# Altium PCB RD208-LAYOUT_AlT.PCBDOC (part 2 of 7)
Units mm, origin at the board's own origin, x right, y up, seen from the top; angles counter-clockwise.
Board outline 240 x 150 mm, 6 copper layers (TOP, Mid-Layer 1, Mid-Layer 2, Mid-Layer 3, Mid-Layer 4, BOTTOM), stack 1.422 mm thick; 773 components, 409 nets, 3936 pads, 97 vias.
Unrouted connection lines stored in the file: 1.
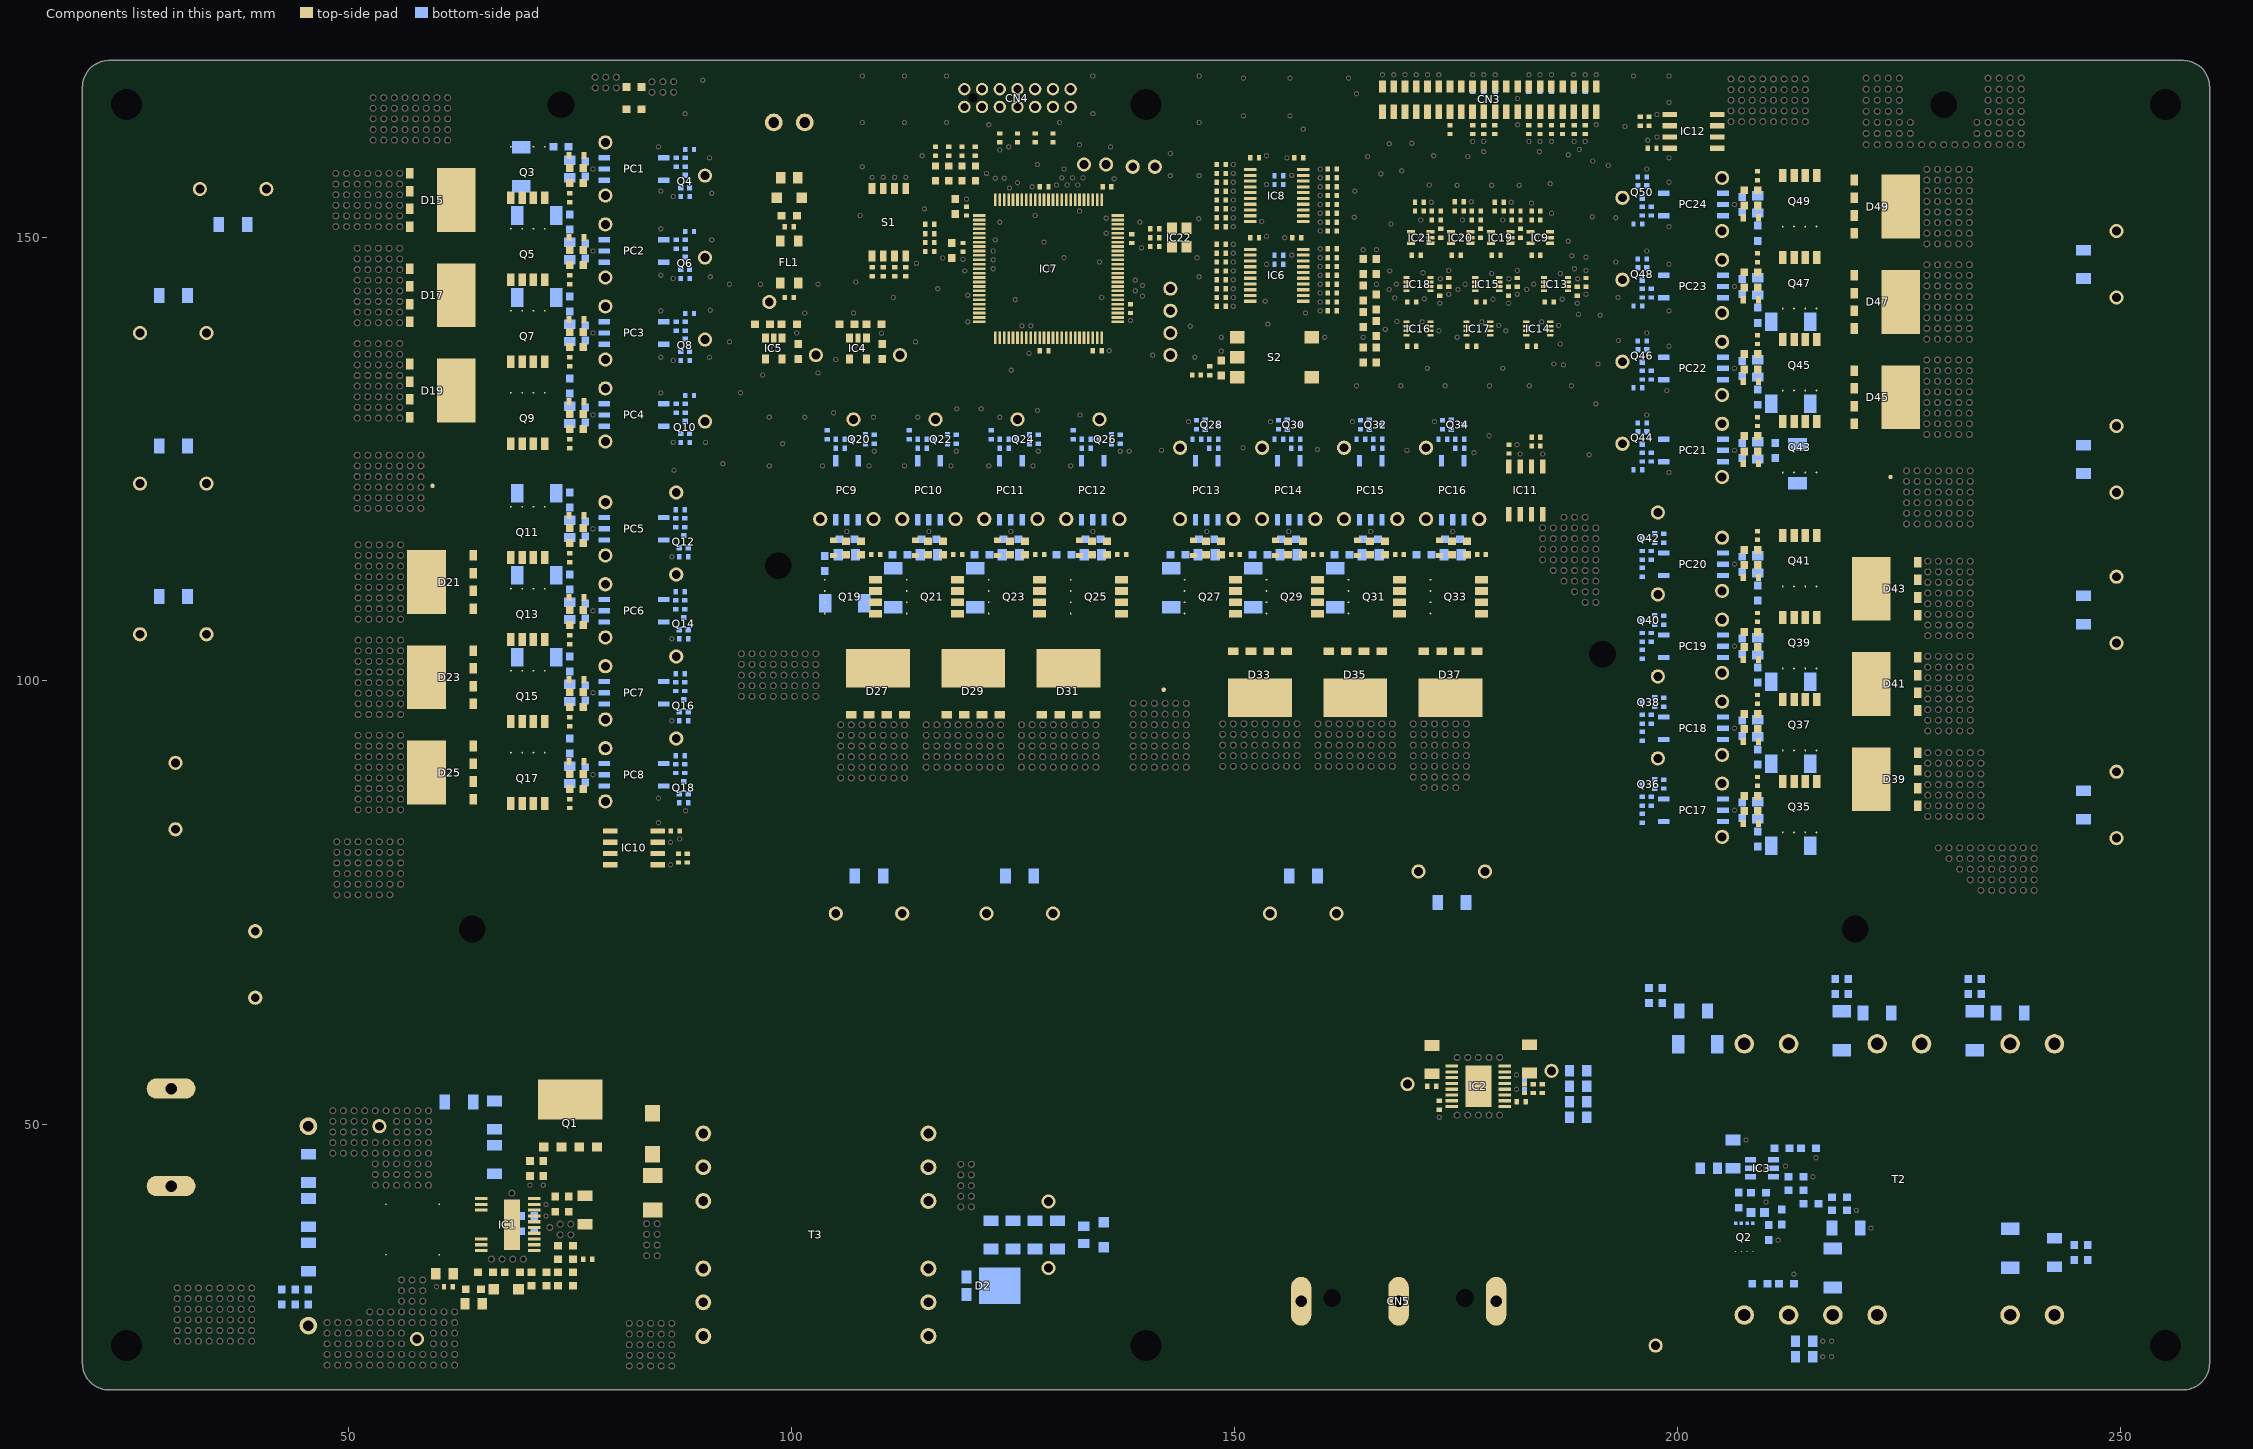
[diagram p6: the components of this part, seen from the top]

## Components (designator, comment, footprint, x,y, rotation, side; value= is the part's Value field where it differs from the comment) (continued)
TP32 "TP-TH1.0-L1.6-D-SP" TP-TH1.0-L1.6-D-SP 79,92.4 r180 top
TP33 "TP-TH1.0-L1.6-D-SP" TP-TH1.0-L1.6-D-SP 107,129.5 r270 top
TP34 "TP-TH1.0-L1.6-D-SP" TP-TH1.0-L1.6-D-SP 116.25,129.5 r270 top
TP35 "TP-TH1.0-L1.6-D-SP" TP-TH1.0-L1.6-D-SP 125.5,129.5 r270 top
TP36 "TP-TH1.0-L1.6-D-SP" TP-TH1.0-L1.6-D-SP 134.75,129.5 r270 top
TP37 "TP-TH1.0-L1.6-D-SP" TP-TH1.0-L1.6-D-SP 143.85,126.3 r270 top
TP38 "TP-TH1.0-L1.6-D-SP" TP-TH1.0-L1.6-D-SP 153.1,126.3 r270 top
TP39 "TP-TH1.0-L1.6-D-SP" TP-TH1.0-L1.6-D-SP 162.35,126.3 r270 top
TP40 "TP-TH1.0-L1.6-D-SP" TP-TH1.0-L1.6-D-SP 171.6,126.3 r270 top
TP41 "TP-TH1.0-L1.6-D-SP" TP-TH1.0-L1.6-D-SP 103.25,118.25 r270 top
TP42 "TP-TH1.0-L1.6-D-SP" TP-TH1.0-L1.6-D-SP 112.5,118.25 r270 top
TP43 "TP-TH1.0-L1.6-D-SP" TP-TH1.0-L1.6-D-SP 121.75,118.25 r270 top
TP44 "TP-TH1.0-L1.6-D-SP" TP-TH1.0-L1.6-D-SP 131,118.25 r270 top
TP45 "TP-TH1.0-L1.6-D-SP" TP-TH1.0-L1.6-D-SP 143.85,118.25 r270 top
TP46 "TP-TH1.0-L1.6-D-SP" TP-TH1.0-L1.6-D-SP 153.1,118.25 r270 top
TP47 "TP-TH1.0-L1.6-D-SP" TP-TH1.0-L1.6-D-SP 162.35,118.25 r270 top
TP48 "TP-TH1.0-L1.6-D-SP" TP-TH1.0-L1.6-D-SP 171.6,118.25 r270 top
TP49 "TP-TH1.0-L1.6-D-SP" TP-TH1.0-L1.6-D-SP 197.75,91.25 r0 top
TP50 "TP-TH1.0-L1.6-D-SP" TP-TH1.0-L1.6-D-SP 197.75,100.5 r0 top
TP51 "TP-TH1.0-L1.6-D-SP" TP-TH1.0-L1.6-D-SP 197.75,109.75 r0 top
TP52 "TP-TH1.0-L1.6-D-SP" TP-TH1.0-L1.6-D-SP 197.75,119 r0 top
TP53 "TP-TH1.0-L1.6-D-SP" TP-TH1.0-L1.6-D-SP 193.75,126.75 r0 top
TP54 "TP-TH1.0-L1.6-D-SP" TP-TH1.0-L1.6-D-SP 193.75,136 r0 top
TP55 "TP-TH1.0-L1.6-D-SP" TP-TH1.0-L1.6-D-SP 193.75,145.25 r0 top
TP56 "TP-TH1.0-L1.6-D-SP" TP-TH1.0-L1.6-D-SP 193.75,154.5 r0 top
TP57 "TP-TH1.0-L1.6-D-SP" TP-TH1.0-L1.6-D-SP 205,82.4 r0 top
TP58 "TP-TH1.0-L1.6-D-SP" TP-TH1.0-L1.6-D-SP 205,91.65 r0 top
TP59 "TP-TH1.0-L1.6-D-SP" TP-TH1.0-L1.6-D-SP 205,100.9 r0 top
TP60 "TP-TH1.0-L1.6-D-SP" TP-TH1.0-L1.6-D-SP 205,110.15 r0 top
TP61 "TP-TH1.0-L1.6-D-SP" TP-TH1.0-L1.6-D-SP 205,123 r0 top
TP62 "TP-TH1.0-L1.6-D-SP" TP-TH1.0-L1.6-D-SP 205,132.25 r0 top
TP63 "TP-TH1.0-L1.6-D-SP" TP-TH1.0-L1.6-D-SP 205,141.5 r0 top
TP64 "TP-TH1.0-L1.6-D-SP" TP-TH1.0-L1.6-D-SP 205,150.75 r0 top
TP65 "TP-TH1.0-L1.6-D-SP" TP-TH1.0-L1.6-D-SP 79,154.75 r180 top
TP66 "TP-TH1.0-L1.6-D-SP" TP-TH1.0-L1.6-D-SP 79,145.5 r180 top
TP67 "TP-TH1.0-L1.6-D-SP" TP-TH1.0-L1.6-D-SP 79,136.25 r180 top
TP68 "TP-TH1.0-L1.6-D-SP" TP-TH1.0-L1.6-D-SP 79,127 r180 top
TP69 "TP-TH1.0-L1.6-D-SP" TP-TH1.0-L1.6-D-SP 79,114.15 r180 top
TP70 "TP-TH1.0-L1.6-D-SP" TP-TH1.0-L1.6-D-SP 79,104.9 r180 top
TP71 "TP-TH1.0-L1.6-D-SP" TP-TH1.0-L1.6-D-SP 79,95.65 r180 top
TP72 "TP-TH1.0-L1.6-D-SP" TP-TH1.0-L1.6-D-SP 79,86.4 r180 top
TP73 "TP-TH1.0-L1.6-D-SP" TP-TH1.0-L1.6-D-SP 109.25,118.25 r270 top
TP74 "TP-TH1.0-L1.6-D-SP" TP-TH1.0-L1.6-D-SP 118.5,118.25 r270 top
TP75 "TP-TH1.0-L1.6-D-SP" TP-TH1.0-L1.6-D-SP 127.75,118.25 r270 top
TP76 "TP-TH1.0-L1.6-D-SP" TP-TH1.0-L1.6-D-SP 137,118.25 r270 top
TP77 "TP-TH1.0-L1.6-D-SP" TP-TH1.0-L1.6-D-SP 149.85,118.25 r270 top
TP78 "TP-TH1.0-L1.6-D-SP" TP-TH1.0-L1.6-D-SP 159.1,118.25 r270 top
TP79 "TP-TH1.0-L1.6-D-SP" TP-TH1.0-L1.6-D-SP 168.35,118.25 r270 top
TP80 "TP-TH1.0-L1.6-D-SP" TP-TH1.0-L1.6-D-SP 177.6,118.25 r270 top
TP81 "TP-TH1.0-L1.6-D-SP" TP-TH1.0-L1.6-D-SP 205,88.4 r0 top
TP82 "TP-TH1.0-L1.6-D-SP" TP-TH1.0-L1.6-D-SP 205,97.65 r0 top
TP83 "TP-TH1.0-L1.6-D-SP" TP-TH1.0-L1.6-D-SP 205,106.9 r0 top
TP84 "TP-TH1.0-L1.6-D-SP" TP-TH1.0-L1.6-D-SP 205,116.15 r0 top
TP85 "TP-TH1.0-L1.6-D-SP" TP-TH1.0-L1.6-D-SP 205,129 r0 top
TP86 "TP-TH1.0-L1.6-D-SP" TP-TH1.0-L1.6-D-SP 205,138.25 r0 top
TP87 "TP-TH1.0-L1.6-D-SP" TP-TH1.0-L1.6-D-SP 205,147.5 r0 top
TP88 "TP-TH1.0-L1.6-D-SP" TP-TH1.0-L1.6-D-SP 205,156.75 r0 top

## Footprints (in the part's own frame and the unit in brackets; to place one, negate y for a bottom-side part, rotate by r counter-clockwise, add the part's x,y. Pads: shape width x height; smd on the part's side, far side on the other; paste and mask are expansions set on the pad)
1843606-D-SP [mm] "KC00080BKP"
  round 2 / inner round 0 / far side round 2 hole 1.2 paste-2.1 mask+0: 1(1.75,0) 2(-1.75,0)
  silkscreen extent -4.2,-4.25 4.2,3
750342424-D-SP [mm] "KC00080BKP"
  round 2.2 / inner round 0 / far side round 2.2 hole 1.4 paste-2.3 mask+0: 1(-17.5,-15.3) 2(-12.5,-15.3) 3(-7.5,-15.3) 4(-2.5,-15.3) 7(12.5,-15.3) 8(17.5,-15.3) 9(17.5,15.3) 10(12.5,15.3) 12(2.5,15.3) 13(-2.5,15.3) 15(-12.5,15.3) 16(-17.5,15.3)
  silkscreen extent -24.5,-20.95 24.5,20.95
878311420-D-SP [mm] "KC00080BKP"
  round 1.4 / inner round 0 / far side round 1.4 hole 0.9 paste-1.5 mask+0: 1(-6,-1) 2(-6,1) 3(-4,-1) 4(-4,1) 5(-2,-1) 6(-2,1) 7(0,-1) 8(0,1) 9(2,-1) 10(2,1) 11(4,-1) 12(4,1) 13(6,-1) 14(6,1)
  round 0 hole 1 unplated paste-1.1 mask+0: ""(5,0)
  silkscreen extent -8.42,-3.25 8.42,3.25
ABRACON-ASE-3.2x2.5-R-SP [mm] "KC00080BKP"
  rect 1.3x1.1 smd paste-1.4 mask+0: 1(-1.05,-0.825) 2(1.05,-0.825) 3(1.05,0.825) 4(-1.05,0.825)
  silkscreen extent -2.1,-1.75 2.1,1.75
C1005_R_SP#1 [mm] "KC00080BKP"
  rect 0.5x0.6 smd paste-0.7 mask+0: 1(-0.5,0) 2(0.5,0)
  silkscreen extent -0.5,-0.65 0.5,0.65
C1005_R_SP#2 [mm] "KC00080BKP"
  rect 0.5x0.6 smd paste-0.7 mask+0: 1(0.5,0) 2(-0.5,0)
C1608_R_SP#1 [mm] "KC00080BKP"
  rect 0.9x0.85 smd paste-1 mask+0: 1(-0.85,0) 2(0.85,0)
  silkscreen extent -0.8,-0.77 0.8,0.77
C1608_R_SP#2 [mm] "KC00080BKP"
  rect 0.9x0.85 smd paste-1 mask+0: 1(0.85,0) 2(-0.85,0)
  silkscreen extent -0.8,-0.77 0.8,0.77
C2125_R_SP#1 [mm] "KC00080BKP"
  rect 1.05x1.3 smd paste-1.4 mask+0: 1(-0.975,0) 2(0.975,0)
C2125_R_SP#2 [mm] "KC00080BKP"
  rect 1.05x1.3 smd paste-1.4 mask+0: 1(0.975,0) 2(-0.975,0)
  silkscreen extent -1,1 1,1
C3216-R-SP#1 [mm] "KC00080BKP"
  rect 1.2x1.7 smd paste-1.8 mask+0: 1(1.6,0) 2(-1.6,0)
  silkscreen extent -1.6,-1.2 1.6,1.2
C3216-R-SP#2 [mm] "KC00080BKP"
  rect 1.2x1.7 smd paste-1.8 mask+0: 1(-1.6,0) 2(1.6,0)
  silkscreen extent -1.6,-1.2 1.6,1.2
C5750-R-SP [mil] "KC00080BKP"
  round 7 smd paste-7 mask+0: 1(-112.2,0) 2(112.2,0)
  silkscreen extent -157,-118 157,118
C-27.0x10.5-P22.5-D-SP [mm] "KC00080BKP"
  round 2 / inner round 0 / far side round 2 hole 1.2 paste-2.1 mask+0: 1(-11.25,0) 2(11.25,0)
  silkscreen extent -13.75,-5.5 13.75,5.5
CA-D18.0-P7.5-D-SP [mm] "KC00080BKP"
  round 1.6 / inner round 0 / far side round 1.6 hole 1 paste-1.7 mask+0: 1(-3.75,0) 2(3.75,0)
  silkscreen extent -10.7,-9.25 9.25,9.25
CA-NICHEMI-D16.0-P7.5-D-SP [mm] "KC00080BKP"
  round 1.6 / inner round 0 / far side round 1.6 hole 1 paste-1.7 mask+0: 1(-3.75,0) 2(3.75,0)
  silkscreen extent -9.7,-8.25 8.25,8.25
CHS-04TB-R-SP [mm] "KC00080BKP"
  rect 0.76x1.27 smd paste-1.37 mask+0: 1(-1.905,-3.81) 2(-0.635,-3.81) 3(0.635,-3.81) 4(1.905,-3.81) 5(1.905,3.81) 6(0.635,3.81) 7(-0.635,3.81) 8(-1.905,3.81)
  silkscreen extent -3.44,-2.8 3.46,2.8
D-ROHM-1608-R-SP [mm] "KC00080BKP"
  rect 0.8x0.8 smd paste-0.9 mask+0: A(-0.825,0) K(0.825,0)
  silkscreen extent -1.65,-0.85 2.1,0.85
DIODES-D-FLAT-R-SP [mm] "KC00080BKP"
  rect 1.85x1.7 smd paste-1.95 mask+0: A(-2.325,0) K(2.325,0)
  silkscreen extent -3.65,-1.46 4.05,1.46
FTSH-120-04-x-DH-A-AEP-R-SP [mm] "KC00080BKP"
  rect 0.75x1.36 smd paste-1.46 mask+0: 1(12.065,-3.375) 3(10.795,-3.375) 5(9.525,-3.375) 7(8.255,-3.375) 9(6.985,-3.375) 11(5.715,-3.375) 13(4.445,-3.375) 15(3.175,-3.375) 17(1.905,-3.375) 19(0.635,-3.375) 21(-0.635,-3.375) 23(-1.905,-3.375) 25(-3.175,-3.375) 27(-4.445,-3.375) 29(-5.715,-3.375) 31(-6.985,-3.375) 33(-8.255,-3.375) 35(-9.525,-3.375) 37(-10.795,-3.375) 39(-12.065,-3.375)
  rect 0.75x1.62 smd paste-1.72 mask+0: 2(12.065,-6.245) 4(10.795,-6.245) 6(9.525,-6.245) 8(8.255,-6.245) 10(6.985,-6.245) 12(5.715,-6.245) 14(4.445,-6.245) 16(3.175,-6.245) 18(1.905,-6.245) 20(0.635,-6.245) 22(-0.635,-6.245) 24(-1.905,-6.245) 26(-3.175,-6.245) 28(-4.445,-6.245) 30(-5.715,-6.245) 32(-6.985,-6.245) 34(-8.255,-6.245) 36(-9.525,-6.245) 38(-10.795,-6.245) 40(-12.065,-6.245)
  silkscreen extent -12.85,-1.4 12.85,-0.85
LT-20-Lead-Plastic-TSSOP-FE-R-SP-17p [mm] "KC00080BKP"
  rect 0.35x1.425 smd paste-1.525 mask+0: 1(-2.925,-2.988) 2(-2.275,-2.988) 3(-1.625,-2.988) 8(1.625,-2.988) 9(2.275,-2.988) 10(2.925,-2.988) 11(2.925,2.987) 12(2.275,2.987) 13(1.625,2.987) 14(0.975,2.987) 15(0.325,2.987) 16(-0.325,2.987) 17(-0.975,2.987) 18(-1.625,2.987) 19(-2.275,2.987) 20(-2.925,2.987)
  rect 5.68x1.78 smd paste-5.68 mask+0: 21(0,0.47)
  silkscreen extent -3.6,-1.9 3.3,1.9
LT-TSOT-23-6-R-SP [mm] "KC00080BKP"
  rect 0.62x1.22 smd paste-1.32 mask+0: 1(0.95,1.31) 2(0,1.31) 3(-0.95,1.31) 4(-0.95,-1.31) 5(0,-1.31) 6(0.95,-1.31)
  silkscreen extent -1.6,-2.3 1.6,2.28
LT-TSSOP-16-FE-R-SP [mm] "KC00080BKP"
  rect 0.35x1.425 smd paste-1.525 mask+0: 1(-2.275,-2.987) 2(-1.625,-2.987) 3(-0.975,-2.987) 4(-0.325,-2.987) 5(0.325,-2.987) 6(0.975,-2.987) 7(1.625,-2.987) 8(2.275,-2.987) 9(2.275,2.987) 10(1.625,2.987) 11(0.975,2.987) 12(0.325,2.987) 13(-0.325,2.987) 14(-0.975,2.987) 15(-1.625,2.987) 16(-2.275,2.987)
  rect 4.7x2.94 smd paste-4.7 mask+0: 17(0,0)
  silkscreen extent -2.75,-1.9 2.75,1.9
ON-PQFN4-8x8-2P-R-SP [mm] "KC00080BKP"
  rect 1.2x0.85 smd paste-1.3 mask+0: 1(-3,-3.825) 2(-1,-3.825) 3(1,-3.825) 4(3,-3.825)
  rect 7.2x4.35 smd paste-7.2 mask+0: 5(0,1.425)
  silkscreen extent -4.1,-4.1 4.1,4.1
ON-TO-227-3LD-123-R-SP [mm] "KC00080BKP"
  rect 1.15x1.45 smd paste-1.55 mask+0: 1(-2.75,-0.985) 2(-2.75,0.985)
  rect 4.65x4.15 smd paste-4.65 mask+0: 3(1,0)
  silkscreen extent -3.7,-2.5 3.7,2.5
ONEPOINT-R-SP#1 [mm] "KC00080BKP"
  round 0.5 smd paste-0.5 mask+0: 1(5.025,2.805) 2(5.025,2.805)
ONEPOINT-R-SP#2 [mm] "KC00080BKP"
  round 0.5 smd paste-0.5 mask+0: 1(-5.25,5.2) 2(-5.25,5.2)
ONEPOINT-R-SP#3 [mm] "KC00080BKP"
  round 0.5 smd paste-0.5 mask+0: 1(-0.5,-2.7) 2(-0.5,-2.7)
OTB-640NS-B-2P-C-D-SP [mm] "KC00080BKP"
  oval 2.3x5.5 / inner round 0 / far side oval 2.3x5.5 hole 1.3 slot 4.5 at 90 deg paste-5.6 mask+0: 1(0,0) 2(11,0)
  silkscreen extent -2.9,-8.65 21.9,8.65
OTB-640NS-B-3P-C-D-SP [mm] "KC00080BKP"
  oval 2.3x5.5 / inner round 0 / far side oval 2.3x5.5 hole 1.3 slot 4.5 at 90 deg paste-5.6 mask+0: 1(0,0) 2(11,0) 3(22,0)
  silkscreen extent -2.9,-8.65 32.9,8.65
R1005_R_SP#1 [mm] "KC00080BKP"
  rect 0.5x0.6 smd paste-0.7 mask+0: 1(-0.5,0) 2(0.5,0)
  silkscreen extent -0.5,-0.65 0.5,-0.65
R1005_R_SP#2 [mm] "KC00080BKP"
  rect 0.5x0.6 smd paste-0.7 mask+0: 1(0.5,0) 2(-0.5,0)
R1608_R_SP#1 [mm] "KC00080BKP"
  rect 0.9x0.85 smd paste-1 mask+0: 1(-0.85,0) 2(0.85,0)
  silkscreen extent -0.8,0.77 0.8,0.77
R1608_R_SP#2 [mm] "KC00080BKP"
  rect 0.9x0.85 smd paste-1 mask+0: 1(0.85,0) 2(-0.85,0)
  silkscreen extent -0.8,-0.77 0.8,0.77
R2125_R_SP [mm] "KC00080BKP"
  rect 1.05x1.3 smd paste-1.4 mask+0: 1(0.975,0) 2(-0.975,0)
  silkscreen extent -1,-1 1,1
R3216-R-SP#1 [mm] "KC00080BKP"
  rect 1.2x1.7 smd paste-1.8 mask+0: 1(1.6,0) 2(-1.6,0)
  silkscreen extent -1.6,-1.2 1.6,1.2
R3216-R-SP#2 [mm] "KC00080BKP"
  rect 1.2x1.7 smd paste-1.8 mask+0: 1(-1.6,0) 2(1.6,0)
  silkscreen extent -1.6,1.2 1.6,1.2
R-WSL0603-R-SP [mm] "KC00080BKP"
  rect 1.02x1.02 smd paste-1.12 mask+0: 1(0.76,0) 2(-0.76,0)
S_LOGO_TOSHIBA [mm] "KC00080BKP"
SKHMQKE010-R-SP [mm] "KC00080BKP"
  rect 1.4x1.6 smd paste-1.7 mask+0: 1(-2.25,-4.2) 2(-2.25,4.2) 3(2.25,-4.2) 4(2.25,4.2) 5(0,4.2)
  silkscreen extent -3.25,-3 3.25,3
SUMIDA-PQ2620-D-SP [mm] "KC00080BKP"
  round 1.8 / inner round 0 / far side round 1.8 hole 1.1 paste-1.9 mask+0: 1(-11.43,-12.7) 2(-7.62,-12.7) 3(-3.81,-12.7) 4(3.81,-12.7) 5(7.62,-12.7) 6(11.43,-12.7) 7(11.43,12.7) 8(7.62,12.7) 9(3.81,12.7) 10(-3.81,12.7) 11(-7.62,12.7) 12(-11.43,12.7)
  silkscreen extent -14,-15.5 14,15.5
TDK-ACM4520-R-SP [mm] "KC00080BKP"
  rect 1.25x0.95 smd paste-1.35 mask+0: 1(-2.375,1) 2(-2.375,-1) 3(2.375,-1) 4(2.375,1)
  silkscreen extent -2.35,-2.35 2.35,2.35
TI-D8-R-SP [mm] "KC00080BKP"
  rect 0.6x1.635 smd paste-1.735 mask+0: 1(-1.905,-2.683) 2(-0.635,-2.683) 3(0.635,-2.683) 4(1.905,-2.683) 5(1.905,2.682) 6(0.635,2.682) 7(-0.635,2.682) 8(-1.905,2.682)
  silkscreen extent -2.5,-1.5 2.5,1.5
TI-DCK5-R-SP [mm] "KC00080BKP"
  rect 0.4x0.9 smd paste-1 mask+0: 1(-0.65,-1.1) 2(0,-1.1) 3(0.65,-1.1) 4(0.65,1.1) 5(-0.65,1.1)
  silkscreen extent -1.21,-1.95 1.21,1.95
TO-2-2H1B-GSD-123-R-SP [mm] "KC00080BKP"
  rect 0.6x0.6 smd paste-0.7 mask+0: 1(0.5,0.7) 2(-0.5,0.7) 3(0,-0.7)
  silkscreen extent -1.15,-1.35 1.15,1.19
TO-2-3X1S-R-SP [mm] "KC00080BKP"
  rect 0.4x0.4 smd paste-0.5 mask+0: 1(0.975,1.55) 2(0.325,1.55) 3(-0.325,1.55) 4(-0.975,1.55)
  round 0.1 smd paste-0.1 mask+0: 5(-0.975,-1.65) 6(-0.325,-1.65) 7(0.325,-1.65) 8(0.975,-1.65)
  silkscreen extent -1.75,-1.75 1.75,1.75
TO-2-5W1A-R-SP [mm] "KC00080BKP"
  rect 0.85x1.45 smd paste-1.55 mask+0: 1(-1.905,-2.75) 2(-0.635,-2.75) 3(0.635,-2.75) 4(1.905,-2.75)
  round 0.2 smd paste-0.2 mask+0: 5(1.905,3) 6(0.635,3) 7(-0.635,3) 8(-1.905,3)
  silkscreen extent -2.7,-3.13 2.7,3.13
TO-2-8T1A-R-SP [mm] "KC00080BKP"
  rect 1.1x1 smd paste-1.2 mask+0: 1(-3,-3.925) 2(-1,-3.925) 3(1,-3.925) 4(3,-3.925)
  rect 7.3x4.5 smd paste-7.3 mask+0: 5(0,1.425)
  silkscreen extent -4.1,-4.1 4.1,4.1
TO-3-2A1A-12-R-SP [mm] "KC00080BKP"
  rect 1.2x1.2 smd paste-1.3 mask+0: 1(-1.4,0) 2(1.4,0)
  silkscreen extent -2.35,-0.95 2.65,0.95
TO-3-2A1S-R-SP#1 [mm] "KC00080BKP"
  rect 1.2x1.2 smd paste-1.3 mask+0: A(1.4,0) K(-1.4,0)
  silkscreen extent -2.8,-1 2.4,1
TO-3-2A1S-R-SP#2 [mm] "KC00080BKP"
  rect 1.2x1.2 smd paste-1.3 mask+0: A(-1.4,0) K(1.4,0)
  silkscreen extent -2.4,-1 2.8,1
TO-3-4E1A-R-SP [mm] "KC00080BKP"
  rect 1.4x2.1 smd paste-2.2 mask+0: A(2.2,0) K(-2.2,0)
  silkscreen extent -3.3,-1.4 3.3,1.4
TO-3-4E1S-R-SP [mm] "KC00080BKP"
  rect 1.4x2.1 smd paste-2.2 mask+0: A(2.2,0) K(-2.2,0)
  silkscreen extent -3.3,-1.4 3.3,1.4
TO-11-4L1S-R-SP [mm] "KC00080BKP"
  rect 0.6x1.3 smd paste-1.4 mask+0: 1(1.27,3.35) 3(-1.27,3.35) 4(-1.27,-3.35) 5(0,-3.35) 6(1.27,-3.35)
  silkscreen extent -2,-2.3 2,2.3
TO-ESC-R-SP [mm] "KC00080BKP"
  rect 0.6x0.8 smd paste-0.9 mask+0: A(-0.85,0) K(0.85,0)
  silkscreen extent 1.46,-0.75 1.9,0.75
TO-SSOP5-P-0.95-R-SP [mm] "KC00080BKP"
  rect 0.8x1 smd paste-1.1 mask+0: 1(-0.95,-1.2) 3(0.95,-1.2) 4(0.95,1.2) 5(-0.95,1.2)
  rect 0.6x1 smd paste-1.1 mask+0: 2(0,-1.2)
  silkscreen extent -1.75,-1.97 1.75,2.1
TO-SSOP8-P-0.50A-R-SP [mm] "KC00080BKP"
  rect 0.3x0.7 smd paste-0.8 mask+0: 1(-0.75,-1.35) 2(-0.25,-1.35) 3(0.25,-1.35) 4(0.75,-1.35) 5(0.75,1.35) 6(0.25,1.35) 7(-0.25,1.35) 8(-0.75,1.35)
  silkscreen extent -1.05,-0.6 1.05,0.6
TO-TSSOP20B-R-SP [mm] "KC00080BKP"
  rect 0.35x1.4 smd paste-1.5 mask+0: 1(-2.925,-3) 2(-2.275,-3) 3(-1.625,-3) 4(-0.975,-3) 5(-0.325,-3) 6(0.325,-3) 7(0.975,-3) 8(1.625,-3) 9(2.275,-3) 10(2.925,-3) 11(2.925,3) 12(2.275,3) 13(1.625,3) 14(0.975,3) 15(0.325,3) 16(-0.325,3) 17(-0.975,3) 18(-1.625,3) 19(-2.275,3) 20(-2.925,3)
  silkscreen extent -3.45,-1.9 3.45,1.9
TP-TH1.0-L1.6-D-SP [mm] "KC00080BKP"
  round 1.6 / inner round 0 / far side round 1.6 hole 1 paste-1.7 mask+0: 1(0,0)
  silkscreen extent -1.3,-1.3 1.3,1.3
V2125-R-SP [mm] "KC00080BKP"
  rect 1.05x1.3 smd paste-1.4 mask+0: 1(-0.975,0) 2(0.975,0)
  silkscreen extent -1,-1 1,1
VISHAY-DO-214AA-R-SP [mm] "KC00080BKP"
  rect 1.716x2.18 smd paste-2.28 mask+0: A(-1.937,0) K(1.937,0)
  silkscreen extent -3.3,-2 3.65,2
XI-VQFP100-R-SP [mm] "KC00080BKP"
  rect 0.3x1.4 smd paste-1.5 mask+0: 1(-6,-7.8) 2(-5.5,-7.8) 3(-5,-7.8) 4(-4.5,-7.8) 5(-4,-7.8) 6(-3.5,-7.8) 7(-3,-7.8) 8(-2.5,-7.8) 9(-2,-7.8) 10(-1.5,-7.8) 11(-1,-7.8) 12(-0.5,-7.8) 13(0,-7.8) 14(0.5,-7.8) 15(1,-7.8) 16(1.5,-7.8) 17(2,-7.8) 18(2.5,-7.8) 19(3,-7.8) 20(3.5,-7.8) 21(4,-7.8) 22(4.5,-7.8) 23(5,-7.8) 24(5.5,-7.8) 25(6,-7.8) 51(6,7.8) 52(5.5,7.8) 53(5,7.8) 54(4.5,7.8) 55(4,7.8) 56(3.5,7.8) 57(3,7.8) 58(2.5,7.8) 59(2,7.8) 60(1.5,7.8) 61(1,7.8) 62(0.5,7.8) 63(0,7.8) 64(-0.5,7.8) 65(-1,7.8) 66(-1.5,7.8) 67(-2,7.8) 68(-2.5,7.8) 69(-3,7.8) 70(-3.5,7.8) 71(-4,7.8) 72(-4.5,7.8) 73(-5,7.8) 74(-5.5,7.8) 75(-6,7.8)
  rect 1.4x0.3 smd paste-1.5 mask+0: 26(7.8,-6) 27(7.8,-5.5) 28(7.8,-5) 29(7.8,-4.5) 30(7.8,-4) 31(7.8,-3.5) 32(7.8,-3) 33(7.8,-2.5) 34(7.8,-2) 35(7.8,-1.5) 36(7.8,-1) 37(7.8,-0.5) 38(7.8,0) 39(7.8,0.5) 40(7.8,1) 41(7.8,1.5) 42(7.8,2) 43(7.8,2.5) 44(7.8,3) 45(7.8,3.5) 46(7.8,4) 47(7.8,4.5) 48(7.8,5) 49(7.8,5.5) 50(7.8,6) 76(-7.8,6) 77(-7.8,5.5) 78(-7.8,5) 79(-7.8,4.5) 80(-7.8,4) 81(-7.8,3.5) 82(-7.8,3) 83(-7.8,2.5) 84(-7.8,2) 85(-7.8,1.5) 86(-7.8,1) 87(-7.8,0.5) 88(-7.8,0) 89(-7.8,-0.5) 90(-7.8,-1) 91(-7.8,-1.5) 92(-7.8,-2) 93(-7.8,-2.5) 94(-7.8,-3) 95(-7.8,-3.5) 96(-7.8,-4) 97(-7.8,-4.5) 98(-7.8,-5) 99(-7.8,-5.5) 100(-7.8,-6)
  silkscreen extent -6.65,-6.65 6.65,6.65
